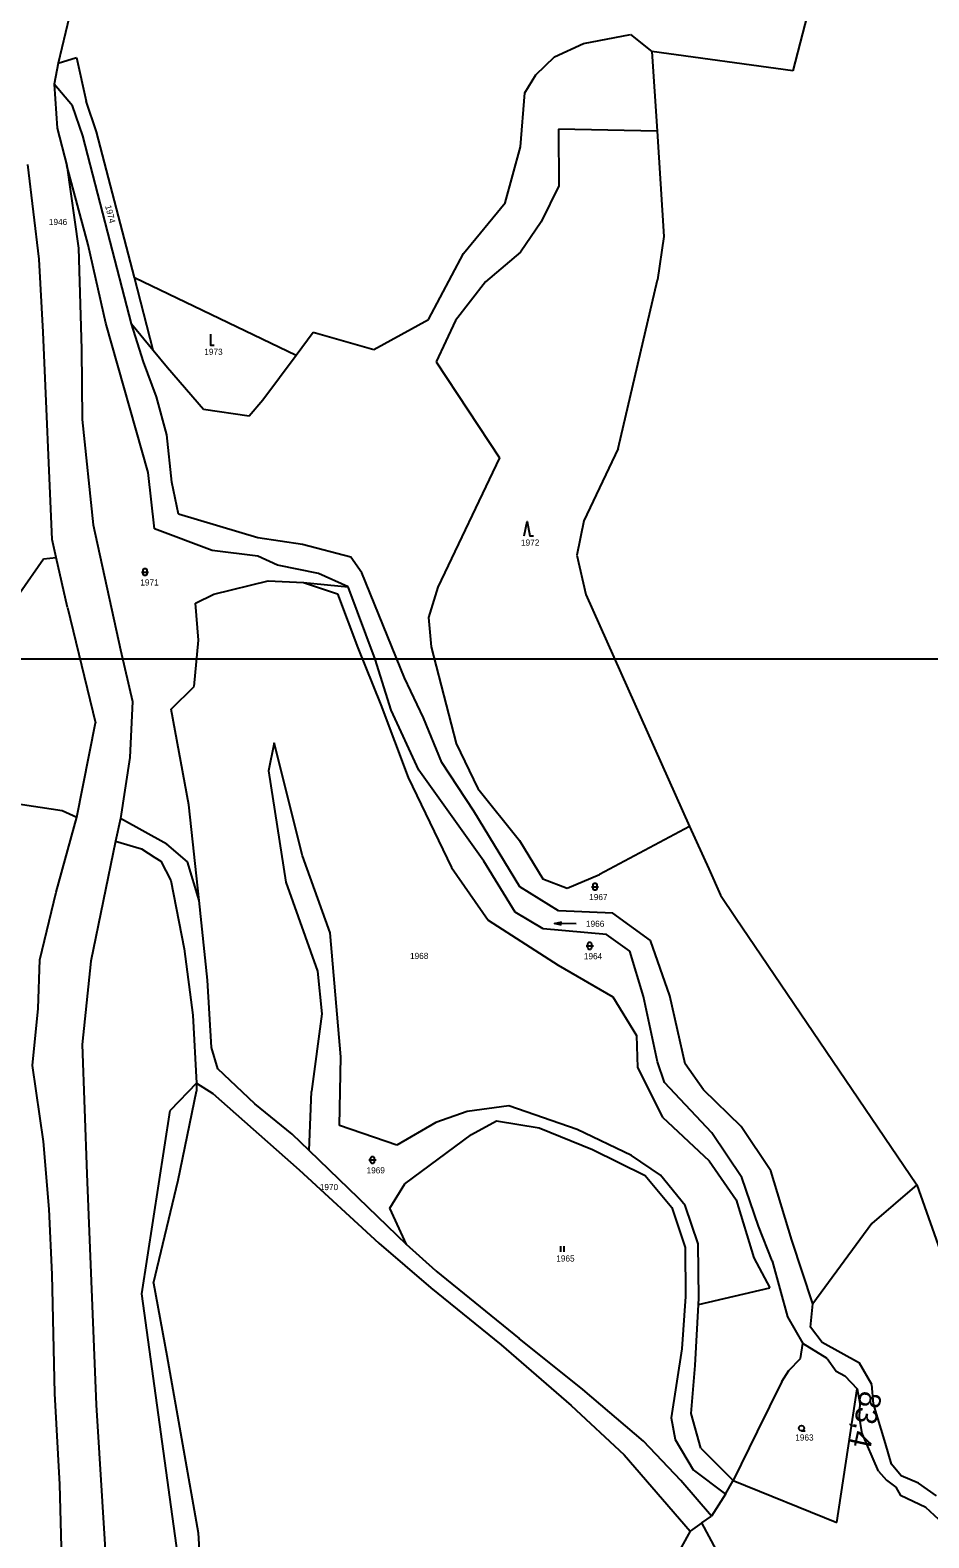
# Model space of a CAD drawing. Extents: x -801853 to -800578, y -1017479 to -1016338.
# Drawn here: x -801418.1 to -801170.2, y -1016987.3 to -1016571.7 of the extents above; entities that cross this region are included whole.
import ezdxf

# ---------------------------------------------------------------- set-up
doc = ezdxf.new("R2010")
doc.units = 0
for name, color, linetype in [('Default', 7, 'Continuous'), ('KN_HRANICE', 7, 'Continuous'), ('KN_KULTURY', 7, 'Continuous'), ('KN_PARCELY', 7, 'Continuous'), ('LEGENDA', 7, 'Continuous'), ('Vrstva 7', 7, 'Continuous'), ('Železniční svršek', 7, 'Continuous')]:
    doc.layers.add(name, color=color, linetype=linetype)

# ---------------------------------------------------------------- blocks, each defined once
blk = doc.blocks.new('302')
at = {"layer": 'Default'}
blk.add_lwpolyline([(0, 3), (0, 0), (1, 0)], dxfattribs=at)
blk = doc.blocks.new('304')
at = {"layer": 'Default'}
blk.add_lwpolyline([(0, 0), (-0.38, 0.1), (-0.65, 0.37), (-0.75, 0.74), (-0.65, 1.11), (-0.38, 1.38), (-0.01, 1.48), (0.36, 1.38), (0.63, 1.11), (0.73, 0.73), (0.63, 0.35), (0.36, 0.08), (-0.02, -0.02), (0.98, -0.02)], dxfattribs=at)
blk = doc.blocks.new('306')
at = {"layer": 'Default'}
for p, q in [((-0.5, 1.5), (-0.5, 0)), ((0.5, 0), (0.5, 1.5))]:
    blk.add_line(p, q, dxfattribs=at)
blk = doc.blocks.new('308')
at = {"layer": 'Default'}
blk.add_lwpolyline([(-0.75, 0), (0, 4), (0.75, 0), (1.75, 0)], dxfattribs=at)
blk = doc.blocks.new('316')
at = {"layer": 'Default'}
for points in [[(-1, 1), (0.27, 1), (1, 1)], [(-0.5, 1.5), (-0.4, 1.79), (-0.15, 1.97), (0.16, 1.97), (0.41, 1.79), (0.51, 1.5), (0.51, 0.5), (0.41, 0.21), (0.16, 0.03), (-0.15, 0.03), (-0.4, 0.21), (-0.5, 0.5), (-0.5, 1.5)]]:
    blk.add_lwpolyline(points, dxfattribs=at)
blk = doc.blocks.new('802')
at = {"layer": 'Default'}
blk.add_line((-3, 0), (3, 0), dxfattribs=at)
blk.add_lwpolyline([(1, 0.5), (3, 0), (1, -0.5)], dxfattribs=at)

msp = doc.modelspace()

# ---------------------------------------------------------------- linework, layer by layer
at = {"layer": 'KN_HRANICE'}
for p, q in [((-801196.12, -1016537.94), (-801207.69, -1016582.91)), ((-801407.27, -1016568.09), (-801410.39, -1016580.85)), ((-801265.48, -1016575.38), (-801252.47, -1016572.88)), ((-801252.47, -1016572.88), (-801246.59, -1016577.62)), ((-801273.5, -1016579.11), (-801265.48, -1016575.38)), ((-801246.59, -1016577.62), (-801245.16, -1016599.53)), ((-801207.69, -1016582.91), (-801246.59, -1016577.62)), ((-801410.39, -1016580.85), (-801411.45, -1016586.58)), ((-801410.39, -1016580.85), (-801405.28, -1016579.28)), ((-801405.28, -1016579.28), (-801402.61, -1016591.33)), ((-801278.62, -1016584.04), (-801273.5, -1016579.11)), ((-801281.61, -1016589.02), (-801278.62, -1016584.04)), ((-801411.45, -1016586.58), (-801410.59, -1016598.71)), ((-801406.4, -1016592.62), (-801411.45, -1016586.58)), ((-801282.88, -1016603.88), (-801281.61, -1016589.02)), ((-801403.57, -1016600.89), (-801406.4, -1016592.62)), ((-801399.74, -1016599.74), (-801402.61, -1016591.33)), ((-801410.59, -1016598.71), (-801407.95, -1016609.05)), ((-801396.67, -1016627.51), (-801403.57, -1016600.89)), ((-801389.32, -1016639.93), (-801399.74, -1016599.74)), ((-801245.16, -1016599.53), (-801272.31, -1016599.02)), ((-801272.31, -1016599.02), (-801272.29, -1016614.6)), ((-801245.16, -1016599.53), (-801243.27, -1016628.57)), ((-801287.04, -1016619.33), (-801282.88, -1016603.88)), ((-801415.62, -1016634.88), (-801418.74, -1016608.77)), ((-801407.95, -1016609.05), (-801404.75, -1016631.78)), ((-801402.07, -1016630.88), (-801407.95, -1016609.05)), ((-801272.29, -1016614.6), (-801277.12, -1016624.55)), ((-801298.6, -1016633.32), (-801287.04, -1016619.33)), ((-801390.11, -1016652.67), (-801396.67, -1016627.51)), ((-801277.12, -1016624.55), (-801282.8, -1016632.88)), ((-801404.75, -1016631.78), (-801403.95, -1016659.67)), ((-801397.17, -1016652.47), (-801402.07, -1016630.88)), ((-801243.27, -1016628.57), (-801245.06, -1016640.51)), ((-801414.44, -1016654.93), (-801415.62, -1016634.88)), ((-801308.25, -1016651.49), (-801298.6, -1016633.32)), ((-801282.8, -1016632.88), (-801292.46, -1016641.08)), ((-801384.13, -1016659.93), (-801389.32, -1016639.93)), ((-801389.32, -1016639.93), (-801344.74, -1016661.3)), ((-801292.46, -1016641.08), (-801300.77, -1016651.72)), ((-801255.91, -1016687.07), (-801245.06, -1016640.51)), ((-801385.5, -1016693.61), (-801397.17, -1016652.47)), ((-801386.82, -1016663.1), (-801390.11, -1016652.67)), ((-801390.11, -1016652.67), (-801384.13, -1016659.93)), ((-801323.26, -1016659.76), (-801308.25, -1016651.49)), ((-801300.77, -1016651.72), (-801306.09, -1016663.1)), ((-801411.98, -1016712.14), (-801414.44, -1016654.93)), ((-801344.74, -1016661.3), (-801340.05, -1016654.98)), ((-801340.05, -1016654.98), (-801323.26, -1016659.76)), ((-801403.95, -1016659.67), (-801403.72, -1016679)), ((-801384.13, -1016659.93), (-801380.18, -1016664.72)), ((-801383.23, -1016672.78), (-801386.82, -1016663.1)), ((-801380.18, -1016664.72), (-801370.23, -1016676.2)), ((-801353.89, -1016673.62), (-801344.74, -1016661.3)), ((-801306.09, -1016663.1), (-801288.67, -1016689.61)), ((-801380.38, -1016683.29), (-801383.23, -1016672.78)), ((-801357.66, -1016678), (-801353.89, -1016673.62)), ((-801370.23, -1016676.2), (-801357.66, -1016678)), ((-801403.72, -1016679), (-801400.68, -1016708.1)), ((-801379, -1016696.34), (-801380.38, -1016683.29)), ((-801288.67, -1016689.61), (-801305.61, -1016725.29)), ((-801255.91, -1016687.07), (-801265.38, -1016707.01)), ((-801383.79, -1016709.22), (-801385.5, -1016693.61)), ((-801377.17, -1016705.1), (-801379, -1016696.34)), ((-801355.25, -1016711.7), (-801377.17, -1016705.1)), ((-801400.68, -1016708.1), (-801393.15, -1016742.52)), ((-801367.9, -1016715.14), (-801383.79, -1016709.22)), ((-801265.38, -1016707.01), (-801267.26, -1016716.41)), ((-801410.87, -1016717.08), (-801411.98, -1016712.14)), ((-801355.3, -1016716.73), (-801367.9, -1016715.14)), ((-801342.96, -1016713.48), (-801355.25, -1016711.7)), ((-801329.61, -1016716.98), (-801342.96, -1016713.48)), ((-801435.35, -1016747.43), (-801414.37, -1016717.41)), ((-801414.37, -1016717.41), (-801410.87, -1016717.08)), ((-801407.76, -1016730.91), (-801410.87, -1016717.08)), ((-801349.81, -1016719.18), (-801355.3, -1016716.73)), ((-801338.55, -1016721.48), (-801349.81, -1016719.18)), ((-801326.57, -1016721.34), (-801329.61, -1016716.98)), ((-801267.26, -1016716.41), (-801264.86, -1016727.26)), ((-801367.4, -1016727.15), (-801352.44, -1016723.55)), ((-801352.44, -1016723.55), (-801342.72, -1016723.96)), ((-801330.35, -1016725.21), (-801338.55, -1016721.48)), ((-801314.87, -1016750.25), (-801326.57, -1016721.34)), ((-801372.5, -1016729.63), (-801367.4, -1016727.15)), ((-801342.72, -1016723.96), (-801333.29, -1016727.12)), ((-801342.72, -1016723.96), (-801330.35, -1016725.21)), ((-801333.29, -1016727.12), (-801327.68, -1016742.01)), ((-801322.92, -1016745.08), (-801330.35, -1016725.21)), ((-801305.61, -1016725.29), (-801308.25, -1016733.62)), ((-801264.86, -1016727.26), (-801236.19, -1016791.22)), ((-801407.76, -1016730.91), (-801400.05, -1016762.62)), ((-801371.61, -1016739.91), (-801372.5, -1016729.63)), ((-801308.25, -1016733.62), (-801307.47, -1016741.69)), ((-801372.85, -1016752.66), (-801371.61, -1016739.91)), ((-801393.15, -1016742.52), (-801389.82, -1016756.82)), ((-801327.68, -1016742.01), (-801321.38, -1016757.65)), ((-801307.47, -1016741.69), (-801300.62, -1016768.35)), ((-801318.5, -1016759.18), (-801322.92, -1016745.08)), ((-801379.21, -1016758.88), (-801372.85, -1016752.66)), ((-801309.57, -1016761.31), (-801314.87, -1016750.25)), ((-801389.82, -1016756.82), (-801390.61, -1016772.19)), ((-801374.32, -1016785.25), (-801379.21, -1016758.88)), ((-801321.38, -1016757.65), (-801313.82, -1016777.7)), ((-801310.89, -1016775.73), (-801318.5, -1016759.18)), ((-801405.24, -1016788.68), (-801400.05, -1016762.62)), ((-801304.52, -1016773.59), (-801309.57, -1016761.31)), ((-801350.77, -1016768.15), (-801352.35, -1016775.89)), ((-801342.98, -1016799.28), (-801350.77, -1016768.15)), ((-801300.62, -1016768.35), (-801294.6, -1016780.8)), ((-801390.61, -1016772.19), (-801393.13, -1016789.06)), ((-801352.35, -1016775.89), (-801347.54, -1016806.61)), ((-801292.99, -1016800.81), (-801310.89, -1016775.73)), ((-801295.75, -1016787.05), (-801304.52, -1016773.59)), ((-801313.82, -1016777.7), (-801301.84, -1016802.52)), ((-801294.6, -1016780.8), (-801283.09, -1016795.11)), ((-801423.24, -1016784.75), (-801409.24, -1016786.85)), ((-801371.48, -1016811.65), (-801374.32, -1016785.25)), ((-801410.88, -1016809.36), (-801405.24, -1016788.68)), ((-801409.24, -1016786.85), (-801405.24, -1016788.68)), ((-801393.13, -1016789.06), (-801394.56, -1016795.27)), ((-801380.37, -1016796.09), (-801393.13, -1016789.06)), ((-801282.99, -1016807.91), (-801295.75, -1016787.05)), ((-801236.19, -1016791.22), (-801261.04, -1016804.5)), ((-801236.19, -1016791.22), (-801230.93, -1016802.94)), ((-801394.56, -1016795.27), (-801401.33, -1016828.35)), ((-801394.56, -1016795.27), (-801387.4, -1016797.43)), ((-801387.4, -1016797.43), (-801383.64, -1016799.76)), ((-801374.7, -1016801.01), (-801380.37, -1016796.09)), ((-801283.09, -1016795.11), (-801276.64, -1016805.63)), ((-801383.64, -1016799.76), (-801382.03, -1016800.75)), ((-801382.03, -1016800.75), (-801379.27, -1016806.1)), ((-801371.48, -1016811.65), (-801374.7, -1016801.01)), ((-801335.34, -1016820.59), (-801342.98, -1016799.28)), ((-801301.84, -1016802.52), (-801291.71, -1016817.07)), ((-801284.31, -1016814.88), (-801292.99, -1016800.81)), ((-801379.27, -1016806.1), (-801375.63, -1016825)), ((-801347.54, -1016806.61), (-801338.83, -1016831.13)), ((-801276.64, -1016805.63), (-801270, -1016808.23)), ((-801270, -1016808.23), (-801261.04, -1016804.5)), ((-801230.93, -1016802.94), (-801227.69, -1016810.17)), ((-801415.36, -1016828.03), (-801410.88, -1016809.36)), ((-801272.38, -1016814.51), (-801282.99, -1016807.91)), ((-801227.69, -1016810.17), (-801223.54, -1016816.29)), ((-801369.16, -1016833.55), (-801371.48, -1016811.65)), ((-801276.59, -1016819.48), (-801284.31, -1016814.88)), ((-801257.35, -1016815.11), (-801272.38, -1016814.51)), ((-801291.71, -1016817.07), (-801272.46, -1016829.44)), ((-801246.96, -1016822.66), (-801257.35, -1016815.11)), ((-801223.54, -1016816.29), (-801173.56, -1016890)), ((-801332.36, -1016854.72), (-801335.34, -1016820.59)), ((-801259.11, -1016821.03), (-801276.59, -1016819.48)), ((-801252.7, -1016825.56), (-801259.11, -1016821.03)), ((-801241.66, -1016837.9), (-801246.96, -1016822.66)), ((-801375.63, -1016825), (-801373.16, -1016843.25)), ((-801248.92, -1016838.05), (-801252.7, -1016825.56)), ((-801415.85, -1016841.4), (-801415.36, -1016828.03)), ((-801401.33, -1016828.35), (-801403.76, -1016851.31)), ((-801338.83, -1016831.13), (-801337.62, -1016842.89)), ((-801272.46, -1016829.44), (-801257.35, -1016838.15)), ((-801368.08, -1016852.12), (-801369.16, -1016833.55)), ((-801257.35, -1016838.15), (-801250.82, -1016848.86)), ((-801245.06, -1016856.14), (-801248.92, -1016838.05)), ((-801237.39, -1016856.65), (-801241.66, -1016837.9)), ((-801417.41, -1016857.13), (-801415.85, -1016841.4)), ((-801373.16, -1016843.25), (-801372.19, -1016862.02)), ((-801337.62, -1016842.89), (-801340.5, -1016864.27)), ((-801403.76, -1016851.31), (-801402.47, -1016886.95)), ((-801366.35, -1016858.03), (-801368.08, -1016852.12)), ((-801250.82, -1016848.86), (-801250.6, -1016857.65)), ((-801332.71, -1016873.66), (-801332.36, -1016854.72)), ((-801243.11, -1016861.82), (-801245.06, -1016856.14)), ((-801414.36, -1016878.03), (-801417.41, -1016857.13)), ((-801356.14, -1016867.7), (-801366.35, -1016858.03)), ((-801250.6, -1016857.65), (-801243.71, -1016871.35)), ((-801232.37, -1016863.85), (-801237.39, -1016856.65)), ((-801372.19, -1016862.02), (-801379.41, -1016869.49)), ((-801377.22, -1016888.71), (-801372.22, -1016864.23)), ((-801372.19, -1016862.02), (-801372.22, -1016864.23)), ((-801372.19, -1016862.02), (-801367.69, -1016864.79)), ((-801367.69, -1016864.79), (-801343.92, -1016885.84)), ((-801341.13, -1016880.54), (-801340.5, -1016864.27)), ((-801230.06, -1016875.69), (-801243.11, -1016861.82)), ((-801222, -1016873.95), (-801232.37, -1016863.85)), ((-801345.81, -1016876.03), (-801356.14, -1016867.7)), ((-801286.09, -1016868.26), (-801297.52, -1016869.84)), ((-801267.25, -1016874.77), (-801286.09, -1016868.26)), ((-801387.26, -1016920.03), (-801379.41, -1016869.49)), ((-801306.18, -1016872.83), (-801316.9, -1016879.08)), ((-801297.52, -1016869.84), (-801306.18, -1016872.83)), ((-801296.32, -1016876.18), (-801289.49, -1016872.35)), ((-801289.49, -1016872.35), (-801277.67, -1016874.3)), ((-801243.71, -1016871.35), (-801230.84, -1016883.39)), ((-801341.13, -1016880.54), (-801345.81, -1016876.03)), ((-801316.9, -1016879.08), (-801332.71, -1016873.66)), ((-801314.72, -1016889.78), (-801296.32, -1016876.18)), ((-801277.67, -1016874.3), (-801262.95, -1016880.25)), ((-801252.23, -1016881.89), (-801267.25, -1016874.77)), ((-801221.82, -1016887.99), (-801230.06, -1016875.69)), ((-801213.83, -1016886.15), (-801222, -1016873.95)), ((-801412.79, -1016896.74), (-801414.36, -1016878.03)), ((-801332.81, -1016888.54), (-801341.13, -1016880.54)), ((-801262.95, -1016880.25), (-801248.49, -1016887.43)), ((-801244.2, -1016887.31), (-801252.23, -1016881.89)), ((-801230.84, -1016883.39), (-801223.31, -1016894.13)), ((-801402.47, -1016886.95), (-801399.88, -1016950.65)), ((-801384.02, -1016917.11), (-801377.22, -1016888.71)), ((-801343.92, -1016885.84), (-801321.91, -1016906.13)), ((-801314.29, -1016906.43), (-801332.81, -1016888.54)), ((-801318.83, -1016896.43), (-801314.72, -1016889.78)), ((-801248.49, -1016887.43), (-801241.1, -1016896.25)), ((-801237.42, -1016895.71), (-801244.2, -1016887.31)), ((-801217.2, -1016901.37), (-801221.82, -1016887.99)), ((-801208, -1016905.29), (-801213.83, -1016886.15)), ((-801173.56, -1016890), (-801185.97, -1016900.67)), ((-801173.56, -1016890), (-801157.02, -1016936.79)), ((-801412.02, -1016914.76), (-801412.79, -1016896.74)), ((-801314.29, -1016906.43), (-801318.83, -1016896.43)), ((-801241.1, -1016896.25), (-801237.39, -1016907.27)), ((-801233.81, -1016906.24), (-801237.42, -1016895.71)), ((-801223.31, -1016894.13), (-801218.46, -1016910.15)), ((-801213.44, -1016910.95), (-801217.2, -1016901.37)), ((-801185.97, -1016900.67), (-801202.21, -1016922.85)), ((-801321.91, -1016906.13), (-801307.61, -1016918.38)), ((-801306.18, -1016913.74), (-801314.29, -1016906.43)), ((-801233.68, -1016921.23), (-801233.81, -1016906.24)), ((-801202.21, -1016922.85), (-801208, -1016905.29)), ((-801237.39, -1016907.27), (-801237.33, -1016920.82)), ((-801218.46, -1016910.15), (-801214.06, -1016918.38)), ((-801411.25, -1016947.54), (-801412.02, -1016914.76)), ((-801306.18, -1016913.74), (-801283.23, -1016932.34)), ((-801213.44, -1016910.95), (-801209.21, -1016926.4)), ((-801384.02, -1016917.11), (-801380.41, -1016937.07)), ((-801307.61, -1016918.38), (-801288.2, -1016934.1)), ((-801233.77, -1016922.99), (-801214.06, -1016918.38)), ((-801376.54, -1016997.57), (-801387.26, -1016920.03)), ((-801237.33, -1016920.82), (-801238.33, -1016935.25)), ((-801234.66, -1016939.84), (-801233.77, -1016922.99)), ((-801233.77, -1016922.99), (-801233.68, -1016921.23)), ((-801202.84, -1016929.27), (-801202.21, -1016922.85)), ((-801209.21, -1016926.4), (-801204.99, -1016933.78)), ((-801199.62, -1016933.47), (-801202.84, -1016929.27)), ((-801288.2, -1016934.1), (-801268.85, -1016950.86)), ((-801265.6, -1016946.42), (-801283.23, -1016932.34)), ((-801238.33, -1016935.25), (-801241.27, -1016954.27)), ((-801205.59, -1016937.87), (-801204.99, -1016933.78)), ((-801198.22, -1016937.87), (-801204.99, -1016933.78)), ((-801189.32, -1016939.19), (-801199.62, -1016933.47)), ((-801380.41, -1016937.07), (-801371.73, -1016985.95)), ((-801208.82, -1016941.19), (-801205.59, -1016937.87)), ((-801198.22, -1016937.87), (-801195.74, -1016941.4)), ((-801185.94, -1016945.08), (-801189.32, -1016939.19)), ((-801235.8, -1016953), (-801234.66, -1016939.84)), ((-801210.76, -1016944.18), (-801208.82, -1016941.19)), ((-801195.74, -1016941.4), (-801193.35, -1016942.64)), ((-801193.35, -1016942.64), (-801190, -1016946.24)), ((-801409.87, -1016972.62), (-801411.25, -1016947.54)), ((-801248.92, -1016960.67), (-801265.6, -1016946.42)), ((-801210.76, -1016944.18), (-801217.52, -1016958.04)), ((-801195.61, -1016983.11), (-801190, -1016946.24)), ((-801190, -1016946.24), (-801189.23, -1016950.15)), ((-801185.46, -1016950.36), (-801185.94, -1016945.08)), ((-801399.88, -1016950.65), (-801397.37, -1016990.64)), ((-801268.85, -1016950.86), (-801254.2, -1016964.46)), ((-801189.23, -1016950.15), (-801189.39, -1016954.09)), ((-801182.14, -1016961.34), (-801185.46, -1016950.36)), ((-801241.27, -1016954.27), (-801240.16, -1016960.25)), ((-801233.13, -1016962.64), (-801235.8, -1016953)), ((-801189.39, -1016954.09), (-801188.76, -1016958.13)), ((-801240.16, -1016960.25), (-801235.24, -1016968.56)), ((-801217.52, -1016958.04), (-801224.21, -1016971.53)), ((-801184.14, -1016968.93), (-801188.76, -1016958.13)), ((-801254.2, -1016964.46), (-801236.03, -1016985.46)), ((-801238.61, -1016971.5), (-801248.92, -1016960.67)), ((-801233.13, -1016962.64), (-801224.21, -1016971.53)), ((-801180.53, -1016967.01), (-801182.14, -1016961.34)), ((-801235.24, -1016968.56), (-801226.27, -1016975.26)), ((-801177.89, -1016970.27), (-801180.53, -1016967.01)), ((-801409.16, -1017001.88), (-801409.87, -1016972.62)), ((-801230.13, -1016981.38), (-801238.61, -1016971.5)), ((-801226.27, -1016975.26), (-801224.21, -1016971.53)), ((-801224.21, -1016971.53), (-801195.61, -1016983.11)), ((-801184.14, -1016968.93), (-801181.87, -1016971.45)), ((-801181.87, -1016971.45), (-801179.3, -1016973.37)), ((-801173.07, -1016972.28), (-801177.89, -1016970.27)), ((-801168.07, -1016975.74), (-801173.07, -1016972.28)), ((-801226.27, -1016975.26), (-801230.13, -1016981.38)), ((-801179.3, -1016973.37), (-801178.02, -1016975.61)), ((-801171.01, -1016978.97), (-801178.02, -1016975.61)), ((-801165.08, -1016984.43), (-801171.01, -1016978.97)), ((-801232.81, -1016983.18), (-801236.03, -1016985.46)), ((-801232.81, -1016983.18), (-801230.13, -1016981.38)), ((-801228.75, -1016990.75), (-801232.81, -1016983.18)), ((-801371.73, -1016985.95), (-801370.4, -1017006.86)), ((-801236.03, -1016985.46), (-801248.21, -1017007.29))]:
    msp.add_line(p, q, dxfattribs=at)
at = {"layer": 'LEGENDA'}
msp.add_lwpolyline([(-801559.16, -1017339.08), (-800718.16, -1017339.08), (-800718.16, -1016745.08), (-801559.16, -1016745.08)], close=True, dxfattribs=at)
at = {"layer": 'Železniční svršek'}
msp.add_arc((-801431.93, -1016905.94), 345.8, 311.7457, 358.6036, dxfattribs=at)

# ---------------------------------------------------------------- block references
at = {"layer": 'KN_KULTURY'}
for name, p in [('302', (-801368.36, -1016658.52)), ('308', (-801281.03, -1016711.12)), ('316', (-801386.39, -1016722.1)), ('316', (-801262.29, -1016808.83)), ('316', (-801263.73, -1016825.13)), ('316', (-801323.66, -1016884.16)), ('306', (-801271.29, -1016908.45)), ('304', (-801205.35, -1016957.81))]:
    msp.add_blockref(name, p, dxfattribs=at)
at = {"layer": 'KN_KULTURY', "rotation": 179.221198}
msp.add_blockref('802', (-801270.48, -1016817.99), dxfattribs=at)

# ---------------------------------------------------------------- texts
at = {"layer": 'KN_PARCELY'}
for s, p in [('1946', (-801412.91, -1016625.44)), ('1973', (-801370.04, -1016661.22)), ('1972', (-801282.69, -1016713.82)), ('1971', (-801387.68, -1016724.8)), ('1967', (-801263.89, -1016811.53)), ('1966', (-801264.78, -1016818.89)), ('1968', (-801313.3, -1016827.76)), ('1964', (-801265.36, -1016827.83)), ('1969', (-801325.29, -1016886.86)), ('1970', (-801338.19, -1016891.47)), ('1965', (-801272.97, -1016911.15)), ('1963', (-801207.06, -1016960.51))]:
    msp.add_text(s, height=1.7, dxfattribs=at).set_placement(p)
msp.add_text('1974', height=1.7, rotation=284.474, dxfattribs=at).set_placement((-801397.42, -1016620.19))
at = {"layer": 'Vrstva 7'}
msp.add_text('83,4', height=6, rotation=257.8494, dxfattribs=at).set_placement((-801188.95, -1016946.51))

doc.saveas('drawing.dxf')
